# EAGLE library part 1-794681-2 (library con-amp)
Micro MATE-N-LOK Connectors grid 1.5mm Dual Row Through Hole Vertical Metal Through Hole Holddowns Source: ENG_CD_794681_E.pdf
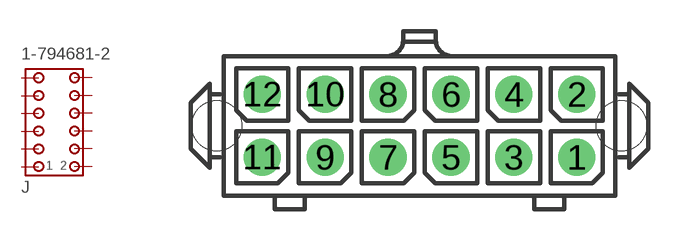
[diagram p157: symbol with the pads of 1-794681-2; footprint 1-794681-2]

Designator prefix J

## 1-794681-2 (MF: TYCO ELECTRONICS; MPN: 1-794681-2; OC_FARNELL: unknown; OC_NEWARK: 10H3810)  [1-794681-2]
1  1  pas
2  2  pas
3  3  pas
4  4  pas
5  5  pas
6  6  pas
7  7  pas
8  8  pas
9  9  pas
10  10  pas
11  11  pas
12  12  pas

## Footprint 1-794681-2 (pad centres in mm)
Micro MATE-N-LOK Connectors grid 1.5mm Dual Row Through Hole Vertical Metal Through Hole Holddowns Source: ENG_CD_794681_E.pdf
drill 1 pad 1.778 round: 1 7.5,-1.5; 2 7.5,1.5; 3 4.5,-1.5; 4 4.5,1.5; 5 1.5,-1.5; 6 1.5,1.5; 7 -1.5,-1.5; 8 -1.5,1.5; 9 -4.5,-1.5; 10 -4.5,1.5; 11 -7.5,-1.5; 12 -7.5,1.5
hole 2.4 at 9.63,0
hole 2.4 at -9.67,0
